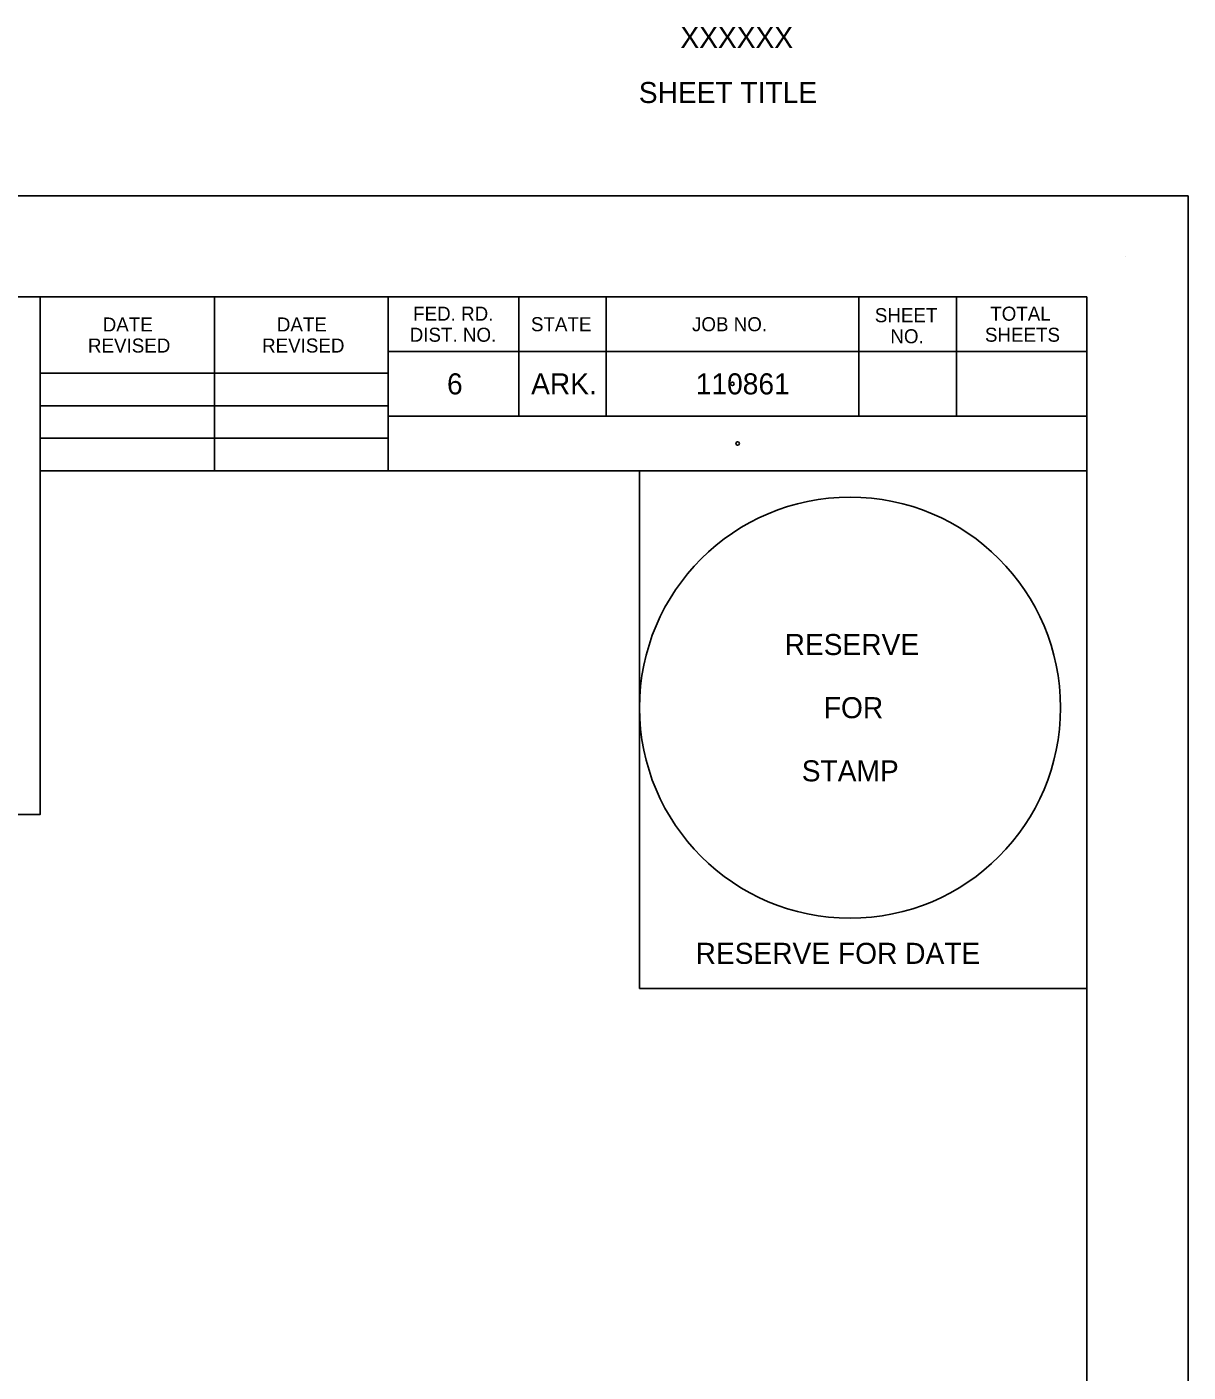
# Model space of a CAD drawing. Extents: x 0 to 19, y -0.6 to 11.5.
# Drawn here: x 13.691 to 17, y 7.648 to 11.481 of the extents above; entities that cross this region are included whole.
import ezdxf

# ---------------------------------------------------------------- set-up
doc = ezdxf.new("R2010")
doc.units = 0
for name, color, linetype in [('G-ANNO-TEXT', 7, 'Continuous'), ('G-Border-Paper', 7, 'Continuous'), ('G-Border-Sheet', 7, 'Continuous'), ('G-No Plot-Anchor', 7, 'Continuous'), ('G-No Plot-Border-1', 7, 'Continuous'), ('G-No Plot-Border-2', 7, 'Continuous'), ('G-No Plot-Stamp-1', 7, 'Continuous'), ('G-Table-Major', 7, 'Continuous'), ('G-Table-Minor', 7, 'Continuous')]:
    doc.layers.add(name, color=color, linetype=linetype)

msp = doc.modelspace()

# ---------------------------------------------------------------- linework, layer by layer
at = {"layer": 'G-ANNO-TEXT'}
msp.add_line((16.821, 10.8269), (16.821, 10.8269), dxfattribs=at)
at = {"layer": 'G-Border-Paper'}
msp.add_lwpolyline([(17, 11), (0, 11), (0, 0), (17, 0)], close=True, dxfattribs=at)
at = {"layer": 'G-Border-Sheet'}
for p in [(0.758, 10.7116), (16.7116, 0.2884)]:
    msp.add_line(p, (16.7116, 10.7116), dxfattribs=at)
at = {"layer": 'G-No Plot-Anchor'}
for centre in [(15.7013, 10.4639), (15.7161, 10.2941)]:
    msp.add_circle(centre, 0.005, dxfattribs=at)
at = {"layer": 'G-No Plot-Border-1'}
msp.add_lwpolyline([(0.758, 0.2884), (0.758, 10.7116), (13.7281, 10.7116), (13.7281, 10.2161), (15.4366, 10.2161), (15.4366, 8.7411), (16.7116, 8.7411), (16.7116, 0.2884)], close=True, dxfattribs=at)
at = {"layer": 'G-No Plot-Border-2'}
msp.add_lwpolyline([(0.758, 0.2884), (0.758, 10.7116), (12.3781, 10.7116), (12.3781, 9.2366), (13.7281, 9.2366), (13.7281, 10.2161), (14.7206, 10.2161), (16.7116, 10.2161), (16.7116, 0.2884)], close=True, dxfattribs=at)
at = {"layer": 'G-No Plot-Stamp-1'}
msp.add_circle((16.0366, 9.5411), 0.6, dxfattribs=at)
at = {"layer": 'G-Table-Major'}
for p, q in [((13.7281, 10.2168), (13.7281, 10.7116)), ((14.7206, 10.7116), (14.7206, 10.2161)), ((13.7281, 10.4946), (14.7206, 10.4946)), ((16.7116, 10.2161), (13.7281, 10.2161))]:
    msp.add_line(p, q, dxfattribs=at)
at = {"layer": 'G-Table-Minor'}
for p, q in [((14.2256, 10.2165), (14.2256, 10.7116)), ((15.0926, 10.7116), (15.0926, 10.3716)), ((15.3411, 10.7116), (15.3411, 10.3716)), ((16.0616, 10.7116), (16.0616, 10.3716)), ((16.3396, 10.7116), (16.3396, 10.3716)), ((16.7116, 10.5561), (14.7206, 10.5561)), ((16.7116, 10.5656), (16.7116, 10.5656)), ((13.7281, 10.4011), (14.7206, 10.4011)), ((16.7116, 10.3716), (14.7206, 10.3716)), ((13.7281, 10.3096), (14.7206, 10.3096))]:
    msp.add_line(p, q, dxfattribs=at)

# ---------------------------------------------------------------- texts
at = {"layer": 'G-ANNO-TEXT'}
for s, height, p in [('XXXXXX', 0.06, (15.5531, 11.4211)), ('SHEET TITLE', 0.06, (15.4345, 11.2641)), ('FED. RD.', 0.04, (14.7913, 10.6439)), ('SHEET', 0.04, (16.1072, 10.6396)), ('TOTAL', 0.04, (16.4361, 10.6439)), ('DATE', 0.04, (13.9066, 10.6131)), ('DATE', 0.04, (14.4029, 10.6131)), ('DIST. NO.', 0.04, (14.7816, 10.5839)), ('STATE', 0.04, (15.1271, 10.6139)), ('JOB NO.', 0.04, (15.5861, 10.6139)), ('NO.', 0.04, (16.1515, 10.5796)), ('SHEETS', 0.04, (16.421, 10.5839)), ('REVISED', 0.04, (13.8646, 10.5531)), ('REVISED', 0.04, (14.3608, 10.5531)), ('6', 0.06, (14.8879, 10.4339)), ('ARK.', 0.06, (15.1276, 10.4339)), ('110861', 0.06, (15.5969, 10.4339))]:
    msp.add_text(s, height=height, dxfattribs=at).set_placement(p)
at = {"layer": 'G-No Plot-Stamp-1'}
for s, p in [('RESERVE', (15.85, 9.6911)), ('FOR ', (15.9617, 9.5111)), ('STAMP', (15.8989, 9.3311)), ('RESERVE FOR DATE', (15.5963, 8.8111))]:
    msp.add_text(s, height=0.06, dxfattribs=at).set_placement(p)

doc.saveas('drawing.dxf')
